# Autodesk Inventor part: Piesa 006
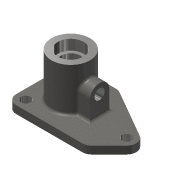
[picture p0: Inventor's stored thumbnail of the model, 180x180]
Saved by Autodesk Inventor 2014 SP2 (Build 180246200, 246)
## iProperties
Created: 2009-01
Part Number: Piesa 006
Document SubType Name: Modeling
Designer: Costel
Material: Steel, Cast
Density: 7.85 g/cm^3
Appearance: Steel - Cast
Mass: 2301.95 g
Surface Area: 538.175 cm^2
Volume: 293.242 cm^3
Author: Costel
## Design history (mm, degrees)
sketch "Sketch1"
  geometry: L1 (-35, 58)-(20.522, 58); L2 (68, -42)-(-35, -42); L3 (-50, -27)-(-50, 43); L4 (-69.56, 0)-(160.784, 0) reference; L5 (0, -55.728)-(0, 92.971) reference; L6 (78.607, -37.607)-(105.607, -10.607); L7 (28.022, 55.99)-(102.5, 12.99); C1 r 7.5 at (-35, 43); C2 r 7.5 at (-35, -27); C3 r 7.5 at (95, 0); A1 r 15 centre (95, 0) between (105.607, -10.607) and (102.5, 12.99); A2 r 15 centre (-35, 43) between (-35, 58) and (-50, 43); A3 r 15 centre (-35, -27) between (-50, -27) and (-35, -42); A4 r 15 centre (68, -27) between (68, -42) and (78.607, -37.607); A5 r 15 centre (20.522, 43) between (28.022, 55.99) and (20.522, 58); 2 further points
  constraints: 10 end point, 10 point on circle, 10 tangent, 8 centre point, 5 point on line, 4 equal radius, 3 coincident, 1 horizontal, 1 parallel
  dimensions: "d0" = 135 deg angle of L6 L2; "d1" = 30 deg angle of L1 L7; "d2" = 15 radius of A1; "d3" = 145 distance from line of L3 A1.centre; "d4" = 42 distance from line of A1.centre L2; "d5" = 100 distance between parallel lines of L2 L1; "d6" = 15 radius of A2; "d7" = 15 diameter of C2; "d14" = 50 distance between parallel lines of L5 L3; "d20" = 15 radius of A4
extrude "Extrusion1" new body sketch "Sketch1" distance "d8" = 12; taper "d9" = 0 deg
sketch "Sketch2"
  geometry: L1 (50, -27)-(50, 43) reference; L2 (66, 0)-(-158, 0) reference; L3 (-68, -42)-(35, -42) reference; C1 r 30 at (0, 8)
  constraints: 1 centre point
  dimensions: "d10" = 50 distance from line of L1 C1.centre; "d11" = 60 diameter of C1; "d39" = 50 distance from line of L3 C1.centre
extrude "Extrusion2" join sketch "Sketch2" distance "d12" = 80; taper "d13" = 0 deg
workplane "Work Plane1"
sketch "Sketch3"
  geometry: L1 (-27, 0)-(43, 0) reference; L2 (-7, 42)-(-7, 0); L3 (23, 42)-(23, 0); L4 (-7, 0)-(23, 0); L5 (-22, 80)-(38, 80) reference; A1 r 15 centre (8, 42) between (23, 42) and (-7, 42); 3 further points; 1 other entity
  constraints: 6 end point, 3 perpendicular, 2 point on circle, 2 point on line, 2 tangent, 1 centre point, 1 midpoint, 1 vertical alignment, 1 other
  dimensions: "d16" = 42 distance from line of L1 A1.centre; "d17" = 15 radius of A1
extrude "Extrusion3" join sketch "Sketch3" stored distance "d18" = 80; taper "d19" = 0 deg
hole "Hole1" diameter "d23" = 30; stored, may be unused: countersink angle "d27" = 90 deg, drill point angle "d29" = 118 deg; dims "d21" = 10, "d22" = 10, "d24" = 6, "d25" = 40, "d26" = 16, "d28" = 30
hole "Hole2" diameter "d32" = 16; stored, may be unused: countersink angle "d36" = 90 deg, drill point angle "d38" = 118 deg; dims "d30" = 10, "d31" = 10, "d33" = 6, "d34" = 40, "d35" = 16, "d37" = 16
fillet "Fillet1" dims "d40" = 4
fillet "Fillet2" dims "d41" = 4
body "Solid1"
node "Projected Loop1"
other parameters: "d15" = 45
